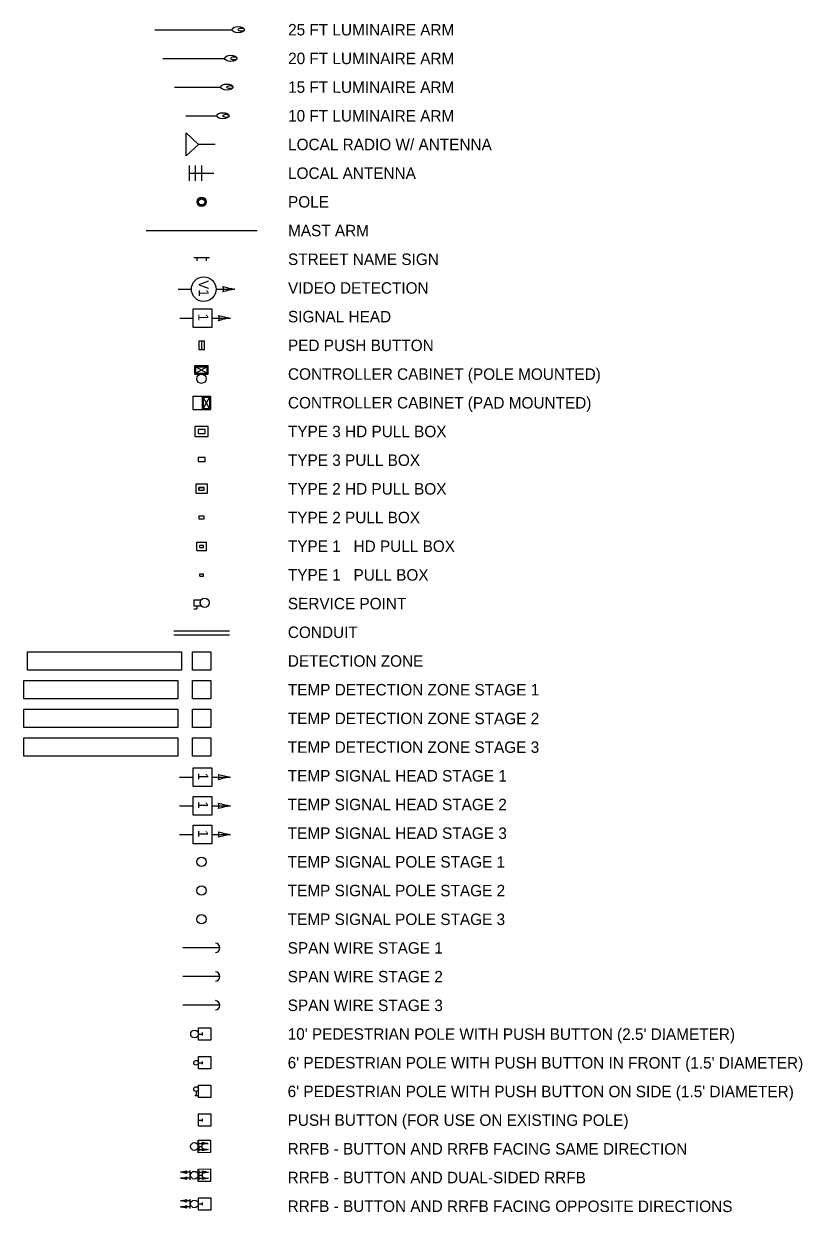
# Model space of a CAD drawing. Extents: x 995815 to 1000702, y 1981720 to 1984760.
# Drawn here: x 997075.9 to 997328.4, y 1983346.4 to 1983731.6 of the extents above; entities that cross this region are included whole.
import ezdxf

# ---------------------------------------------------------------- set-up
doc = ezdxf.new("R2010")
doc.units = 0
for name, color, linetype in [('DSN_Drain_Alignment_ArDOT_BMCD_Rt', 7, 'Continuous'), ('DSN_DRAIN_Analytics', 7, 'Continuous'), ('DSN_DRAIN_Analytics_ArDOT_BMCD_Rt', 7, 'Continuous'), ('DSN_DRAIN_Storm-Sewer_ArDOT_BMCD_Lt', 7, 'Continuous'), ('DSN_DRFT_Common-Annotations', 7, 'Continuous'), ('DSN_DRFT_Const-No-Plot', 7, 'Continuous'), ('DSN_DRFT_Guideline-No-Plot', 7, 'Continuous'), ('DSN_RDWY_Alignment', 7, 'Continuous'), ('DSN_ROW_Point-Name-Annotation', 7, 'Continuous'), ('R_Notes', 7, 'Continuous'), ('TEMP_DETECTION ZONE_STAGE 1', 7, 'Continuous'), ('TEMP_DETECTION ZONE_STAGE 2', 7, 'Continuous'), ('TEMP_DETECTION ZONE_STAGE 3', 7, 'Continuous'), ('TEMP_SIGNAL_HEAD_STAGE 1', 7, 'Continuous'), ('TEMP_SIGNAL_HEAD_STAGE 2', 7, 'Continuous'), ('TEMP_SIGNAL_HEAD_STAGE 3', 7, 'Continuous'), ('TEMP_SIGNAL_POLES_STAGE 1', 7, 'Continuous'), ('TEMP_SIGNAL_POLES_STAGE 2', 7, 'Continuous'), ('TEMP_SIGNAL_POLES_STAGE 3', 7, 'Continuous')]:
    doc.layers.add(name, color=color, linetype=linetype)

msp = doc.modelspace()

# ---------------------------------------------------------------- linework, layer by layer
at = {"layer": 'DSN_Drain_Alignment_ArDOT_BMCD_Rt'}
for p, q in [((997118.45, 1983729.63), (997143.45, 1983729.63)), ((997121.04, 1983720.33), (997141.04, 1983720.33)), ((997124.75, 1983711.03), (997139.75, 1983711.03)), ((997128.47, 1983701.73), (997138.47, 1983701.73)), ((997128.59, 1983688.71), (997128.59, 1983696.21)), ((997128.59, 1983696.21), (997132.59, 1983692.46)), ((997132.59, 1983692.46), (997128.59, 1983688.71)), ((997137.94, 1983692.46), (997132.59, 1983692.46)), ((997129.52, 1983685.62), (997129.52, 1983680.62)), ((997129.52, 1983683.12), (997137.52, 1983683.12)), ((997131.52, 1983685.62), (997131.52, 1983680.62)), ((997133.52, 1983685.62), (997133.52, 1983680.62)), ((997131.35, 1983618.01), (997131.35, 1983620.75)), ((997131.35, 1983620.75), (997135.68, 1983620.75)), ((997135.68, 1983618.01), (997135.68, 1983620.75)), ((997131.35, 1983618.01), (997135.68, 1983618.01)), ((997131.68, 1983620.42), (997135.35, 1983620.42)), ((997131.68, 1983618.34), (997131.68, 1983620.42)), ((997135.35, 1983620.42), (997131.68, 1983618.34)), ((997131.68, 1983618.34), (997135.35, 1983618.34)), ((997131.7, 1983620.42), (997135.35, 1983618.34)), ((997135.35, 1983618.34), (997135.35, 1983620.42)), ((997132, 1983563.59), (997135.18, 1983563.59)), ((997132, 1983560.86), (997132, 1983563.59)), ((997135.18, 1983560.86), (997135.18, 1983563.59)), ((997132, 1983560.86), (997135.18, 1983560.86)), ((997133, 1983561.86), (997133, 1983562.59)), ((997133, 1983562.59), (997134.18, 1983562.59)), ((997133, 1983561.86), (997134.18, 1983561.86)), ((997134.18, 1983561.86), (997134.18, 1983562.59)), ((997133, 1983552.57), (997133, 1983553.3)), ((997133, 1983553.3), (997134.18, 1983553.3)), ((997133, 1983552.57), (997134.18, 1983552.57)), ((997134.18, 1983552.57), (997134.18, 1983553.3))]:
    msp.add_line(p, q, dxfattribs=at)
msp.add_circle((997133.52, 1983616.51), 1.5, dxfattribs=at)
for centre, major_axis in [((997145.45, 1983729.63), (2, 0)), ((997146.45, 1983729.63), (-1, 0)), ((997143.04, 1983720.33), (2, 0)), ((997144.04, 1983720.33), (-1, 0)), ((997141.75, 1983711.03), (2, 0)), ((997142.75, 1983711.03), (-1, 0)), ((997140.47, 1983701.73), (2, 0)), ((997141.47, 1983701.73), (-1, 0))]:
    msp.add_ellipse(centre, major_axis=major_axis, ratio=0.5, dxfattribs=at)
at = {"layer": 'DSN_DRAIN_Analytics'}
for p, q in [((997077.07, 1983528.03), (997127.07, 1983528.03)), ((997077.07, 1983522.03), (997077.07, 1983528.03)), ((997127.07, 1983528.03), (997127.07, 1983522.03)), ((997127.07, 1983522.03), (997077.07, 1983522.03))]:
    msp.add_line(p, q, dxfattribs=at)
msp.add_lwpolyline([(997136.59, 1983522.03), (997130.59, 1983522.03), (997130.59, 1983528.03), (997136.59, 1983528.03)], close=True, dxfattribs=at)
at = {"layer": 'DSN_DRAIN_Analytics_ArDOT_BMCD_Rt'}
for points in [[(997132.54, 1983406.13), (997136.54, 1983406.13), (997136.54, 1983402.13), (997132.54, 1983402.13)], [(997132.53, 1983396.83), (997136.53, 1983396.83), (997136.53, 1983392.83), (997132.53, 1983392.83)], [(997132.53, 1983387.53), (997136.53, 1983387.53), (997136.53, 1983383.53), (997132.53, 1983383.53)], [(997132.52, 1983378.23), (997136.52, 1983378.23), (997136.52, 1983374.23), (997132.52, 1983374.23)], [(997132.48, 1983369.67), (997136.48, 1983369.68), (997136.49, 1983365.68), (997132.49, 1983365.67)], [(997132.5, 1983360.37), (997136.5, 1983360.38), (997136.51, 1983356.38), (997132.51, 1983356.37)], [(997132.52, 1983351.07), (997136.52, 1983351.08), (997136.53, 1983347.08), (997132.53, 1983347.07)]]:
    msp.add_lwpolyline(points, close=True, dxfattribs=at)
at = {"layer": 'DSN_DRAIN_Storm-Sewer_ArDOT_BMCD_Lt'}
for p, q in [((997136.09, 1983655.73), (997131.09, 1983655.73)), ((997132.09, 1983654.73), (997132.09, 1983655.73)), ((997135.09, 1983655.73), (997135.09, 1983654.73)), ((997136.09, 1983655.73), (997135.09, 1983655.73))]:
    msp.add_line(p, q, dxfattribs=at)
at = {"layer": 'DSN_DRFT_Common-Annotations'}
for p, q in [((997135.76, 1983601.06), (997131.43, 1983601.06)), ((997131.43, 1983601.06), (997131.43, 1983597.79)), ((997131.43, 1983597.79), (997135.76, 1983597.79)), ((997132.43, 1983600.06), (997132.43, 1983598.79)), ((997134.76, 1983600.06), (997132.43, 1983600.06)), ((997132.43, 1983598.79), (997134.76, 1983598.79)), ((997134.76, 1983598.79), (997134.76, 1983600.06)), ((997135.76, 1983597.79), (997135.76, 1983601.06)), ((997132.42, 1983590.94), (997132.42, 1983589.67)), ((997134.76, 1983590.94), (997132.42, 1983590.94)), ((997134.76, 1983589.67), (997134.76, 1983590.94)), ((997132.42, 1983589.67), (997134.76, 1983589.67)), ((997135.46, 1983582.29), (997131.71, 1983582.29)), ((997131.71, 1983582.29), (997131.71, 1983579.37)), ((997135.46, 1983579.37), (997135.46, 1983582.29)), ((997131.71, 1983579.37), (997135.46, 1983579.37)), ((997132.71, 1983580.37), (997132.71, 1983581.29)), ((997132.71, 1983581.29), (997134.46, 1983581.29)), ((997132.71, 1983581.29), (997132.71, 1983580.37)), ((997134.46, 1983581.29), (997132.71, 1983581.29)), ((997132.71, 1983580.37), (997134.46, 1983580.37)), ((997132.71, 1983580.37), (997134.46, 1983580.37)), ((997134.46, 1983580.37), (997134.46, 1983581.29)), ((997134.46, 1983580.37), (997134.46, 1983581.29)), ((997132.71, 1983571.99), (997132.71, 1983571.07)), ((997134.46, 1983571.99), (997132.71, 1983571.99)), ((997132.71, 1983571.99), (997132.71, 1983571.07)), ((997134.46, 1983571.99), (997132.71, 1983571.99)), ((997132.71, 1983571.07), (997134.46, 1983571.07)), ((997132.71, 1983571.07), (997134.46, 1983571.07)), ((997134.46, 1983571.07), (997134.46, 1983571.99)), ((997134.46, 1983571.07), (997134.46, 1983571.99)), ((997132.54, 1983404.13), (997133.85, 1983404.13)), ((997133.85, 1983403.7), (997133.85, 1983404.57)), ((997132.53, 1983394.83), (997133.85, 1983394.83)), ((997133.85, 1983394.4), (997133.85, 1983395.27)), ((997131.34, 1983384.21), (997132.21, 1983384.21)), ((997131.78, 1983385.53), (997131.78, 1983384.21)), ((997132.52, 1983376.23), (997133.84, 1983376.23)), ((997133.84, 1983375.8), (997133.84, 1983376.67)), ((997132.49, 1983367.67), (997133.81, 1983367.68)), ((997133.81, 1983367.24), (997133.8, 1983368.11)), ((997133.82, 1983357.94), (997133.82, 1983358.81)), ((997132.5, 1983358.37), (997133.82, 1983358.38)), ((997132.52, 1983349.07), (997133.84, 1983349.08)), ((997133.84, 1983348.64), (997133.84, 1983349.51))]:
    msp.add_line(p, q, dxfattribs=at)
for points in [[(997132.73, 1983628.65), (997132.73, 1983626.02), (997133.6, 1983626.01), (997133.6, 1983628.65)], [(997132.73, 1983626.02), (997134.47, 1983626.01), (997134.48, 1983628.65), (997132.73, 1983628.65)]]:
    msp.add_lwpolyline(points, close=True, dxfattribs=at)
at = {"layer": 'DSN_DRFT_Const-No-Plot'}
for p, q in [((997130.73, 1983610.9), (997136.47, 1983610.9)), ((997130.73, 1983610.9), (997130.73, 1983606.57)), ((997133.73, 1983610.9), (997133.73, 1983606.57)), ((997134.06, 1983610.57), (997134.06, 1983606.9)), ((997136.14, 1983606.9), (997134.06, 1983610.57)), ((997134.06, 1983610.57), (997136.14, 1983610.57)), ((997136.14, 1983610.55), (997134.06, 1983606.9)), ((997136.14, 1983610.57), (997136.14, 1983606.9)), ((997136.47, 1983610.9), (997136.47, 1983606.57)), ((997130.73, 1983606.57), (997136.47, 1983606.57)), ((997134.06, 1983606.9), (997136.14, 1983606.9))]:
    msp.add_line(p, q, dxfattribs=at)
at = {"layer": 'DSN_DRFT_Guideline-No-Plot'}
for p, q in [((997125.94, 1983645.54), (997130.27, 1983645.54)), ((997138.27, 1983645.54), (997144.33, 1983645.54)), ((997126.53, 1983636.16), (997130.87, 1983636.16)), ((997136.94, 1983636.19), (997142.98, 1983636.19))]:
    msp.add_line(p, q, dxfattribs=at)
msp.add_lwpolyline([(997130.87, 1983633.15), (997130.87, 1983639.21), (997136.94, 1983639.21), (997136.94, 1983633.15)], close=True, dxfattribs=at)
msp.add_circle((997134.27, 1983645.54), 4, dxfattribs=at)
for centre, radius, start, end in [((997139.06, 1983645.54), 1.63, 328.1527, 31.8473), ((997148.74, 1983674.68), 29.47, 253.6536, 261.3917), ((997148.74, 1983616.4), 29.47, 98.6083, 106.3464), ((997137.71, 1983636.19), 1.63, 328.1527, 31.8473), ((997147.39, 1983665.33), 29.47, 253.6536, 261.3917), ((997147.39, 1983607.04), 29.47, 98.6083, 106.3464)]:
    msp.add_arc(centre, radius, start, end, dxfattribs=at)
at = {"layer": 'DSN_RDWY_Alignment'}
for p, q in [((997131.08, 1983544.89), (997131.08, 1983542.89)), ((997131.08, 1983544.89), (997133.08, 1983544.89)), ((997133.08, 1983544.89), (997133.08, 1983542.89)), ((997131.08, 1983542.89), (997133.08, 1983542.89)), ((997131.08, 1983541.89), (997132.08, 1983541.89)), ((997132.08, 1983542.89), (997132.08, 1983541.89)), ((997124.52, 1983534.83), (997142.65, 1983534.83)), ((997124.52, 1983533.5), (997142.65, 1983533.5))]:
    msp.add_line(p, q, dxfattribs=at)
msp.add_circle((997134.58, 1983543.89), 1.5, dxfattribs=at)
at = {"layer": 'DSN_ROW_Point-Name-Annotation'}
for p, q in [((997115.59, 1983664.54), (997151.59, 1983664.54)), ((997132.49, 1983367.67), (997132.74, 1983367.67)), ((997132.74, 1983366.17), (997132.73, 1983369.17)), ((997132.74, 1983368.67), (997135.76, 1983368.68)), ((997132.74, 1983366.67), (997135.76, 1983366.68)), ((997129.75, 1983359.37), (997126.73, 1983359.36)), ((997129.75, 1983359.87), (997129.76, 1983356.87)), ((997132.76, 1983356.87), (997132.75, 1983359.87)), ((997132.75, 1983359.37), (997135.77, 1983359.38)), ((997129.76, 1983357.37), (997126.74, 1983357.36)), ((997130, 1983358.37), (997129.75, 1983358.37)), ((997132.5, 1983358.37), (997132.75, 1983358.37)), ((997132.76, 1983357.37), (997135.78, 1983357.38)), ((997129.77, 1983350.08), (997126.75, 1983350.07)), ((997129.77, 1983348.08), (997126.75, 1983348.07)), ((997129.77, 1983350.58), (997129.77, 1983347.58)), ((997130.02, 1983349.08), (997129.77, 1983349.08))]:
    msp.add_line(p, q, dxfattribs=at)
for centre, radius in [((997133.59, 1983673.84), 1.5), ((997133.59, 1983673.84), 1.25), ((997133.59, 1983673.84), 1), ((997133.55, 1983459.93), 1.5), ((997131.29, 1983404.14), 1.25), ((997131.78, 1983394.83), 0.75), ((997131.78, 1983386.28), 0.75), ((997131.24, 1983367.67), 1.25), ((997131.25, 1983358.37), 1.25), ((997131.27, 1983349.07), 1.25)]:
    msp.add_circle(centre, radius, dxfattribs=at)
for centre, radius, start, end in [((997133.12, 1983368.67), 0.814, 328.2824, 31.977), ((997137.93, 1983383.25), 14.74, 253.7833, 261.5214), ((997137.99, 1983354.11), 14.74, 98.738, 106.4762), ((997133.13, 1983366.67), 0.814, 328.2824, 31.977), ((997137.93, 1983381.25), 14.74, 253.7833, 261.5214), ((997138, 1983352.11), 14.74, 98.738, 106.4762), ((997124.49, 1983373.93), 14.74, 278.738, 286.4762), ((997124.56, 1983344.79), 14.74, 73.7833, 81.5214), ((997129.37, 1983359.37), 0.814, 148.2824, 211.977), ((997133.14, 1983359.37), 0.814, 328.2824, 31.977), ((997137.95, 1983373.95), 14.74, 253.7833, 261.5214), ((997138.01, 1983344.81), 14.74, 98.738, 106.4762), ((997124.5, 1983371.93), 14.74, 278.738, 286.4762), ((997124.56, 1983342.79), 14.74, 73.7833, 81.5214), ((997129.37, 1983357.37), 0.814, 148.2824, 211.977), ((997133.14, 1983357.37), 0.814, 328.2824, 31.977), ((997137.95, 1983371.95), 14.74, 253.7833, 261.5214), ((997138.02, 1983342.81), 14.74, 98.738, 106.4762), ((997124.51, 1983364.64), 14.74, 278.738, 286.4762), ((997124.58, 1983335.5), 14.74, 73.7833, 81.5214), ((997124.51, 1983362.64), 14.74, 278.738, 286.4762), ((997124.58, 1983333.5), 14.74, 73.7833, 81.5214), ((997129.38, 1983350.08), 0.814, 148.2824, 211.977), ((997129.39, 1983348.08), 0.814, 148.2824, 211.977)]:
    msp.add_arc(centre, radius, start, end, dxfattribs=at)
at = {"layer": 'TEMP_DETECTION ZONE_STAGE 1'}
for p, q in [((997075.91, 1983518.73), (997125.91, 1983518.73)), ((997075.91, 1983512.73), (997075.91, 1983518.73)), ((997125.91, 1983518.73), (997125.91, 1983512.73)), ((997125.91, 1983512.73), (997075.91, 1983512.73))]:
    msp.add_line(p, q, dxfattribs=at)
msp.add_lwpolyline([(997136.59, 1983512.73), (997130.59, 1983512.73), (997130.59, 1983518.73), (997136.59, 1983518.73)], close=True, dxfattribs=at)
at = {"layer": 'TEMP_DETECTION ZONE_STAGE 2'}
for p, q in [((997075.91, 1983509.43), (997125.91, 1983509.43)), ((997075.91, 1983503.43), (997075.91, 1983509.43)), ((997125.91, 1983509.43), (997125.91, 1983503.43)), ((997125.91, 1983503.43), (997075.91, 1983503.43))]:
    msp.add_line(p, q, dxfattribs=at)
msp.add_lwpolyline([(997136.58, 1983503.43), (997130.58, 1983503.43), (997130.58, 1983509.43), (997136.58, 1983509.43)], close=True, dxfattribs=at)
at = {"layer": 'TEMP_DETECTION ZONE_STAGE 3'}
for p, q in [((997075.9, 1983500.13), (997125.9, 1983500.13)), ((997075.9, 1983494.13), (997075.9, 1983500.13)), ((997125.9, 1983500.13), (997125.9, 1983494.13)), ((997125.9, 1983494.13), (997075.9, 1983494.13))]:
    msp.add_line(p, q, dxfattribs=at)
msp.add_lwpolyline([(997136.58, 1983494.13), (997130.58, 1983494.13), (997130.58, 1983500.13), (997136.58, 1983500.13)], close=True, dxfattribs=at)
at = {"layer": 'TEMP_SIGNAL_HEAD_STAGE 1'}
for p, q in [((997126.46, 1983487.36), (997130.81, 1983487.36)), ((997136.87, 1983487.39), (997142.91, 1983487.39))]:
    msp.add_line(p, q, dxfattribs=at)
msp.add_lwpolyline([(997130.81, 1983484.35), (997130.81, 1983490.41), (997136.87, 1983490.41), (997136.87, 1983484.35)], close=True, dxfattribs=at)
for centre, radius, start, end in [((997137.64, 1983487.39), 1.63, 328.1527, 31.8473), ((997147.32, 1983516.53), 29.47, 253.6536, 261.3917), ((997147.32, 1983458.24), 29.47, 98.6083, 106.3464)]:
    msp.add_arc(centre, radius, start, end, dxfattribs=at)
at = {"layer": 'TEMP_SIGNAL_HEAD_STAGE 2'}
for p, q in [((997126.46, 1983478.06), (997130.8, 1983478.06)), ((997136.87, 1983478.09), (997142.91, 1983478.09))]:
    msp.add_line(p, q, dxfattribs=at)
msp.add_lwpolyline([(997130.8, 1983475.05), (997130.8, 1983481.11), (997136.87, 1983481.11), (997136.87, 1983475.05)], close=True, dxfattribs=at)
for centre, radius, start, end in [((997137.64, 1983478.09), 1.63, 328.1527, 31.8473), ((997147.32, 1983507.23), 29.47, 253.6536, 261.3917), ((997147.32, 1983448.94), 29.47, 98.6083, 106.3464)]:
    msp.add_arc(centre, radius, start, end, dxfattribs=at)
at = {"layer": 'TEMP_SIGNAL_HEAD_STAGE 3'}
for p, q in [((997126.45, 1983468.76), (997130.8, 1983468.76)), ((997136.86, 1983468.79), (997142.9, 1983468.79))]:
    msp.add_line(p, q, dxfattribs=at)
msp.add_lwpolyline([(997130.8, 1983465.75), (997130.8, 1983471.81), (997136.86, 1983471.81), (997136.86, 1983465.75)], close=True, dxfattribs=at)
for centre, radius, start, end in [((997137.64, 1983468.79), 1.63, 328.1527, 31.8473), ((997147.31, 1983497.93), 29.47, 253.6536, 261.3917), ((997147.31, 1983439.64), 29.47, 98.6083, 106.3464)]:
    msp.add_arc(centre, radius, start, end, dxfattribs=at)
at = {"layer": 'TEMP_SIGNAL_POLES_STAGE 1'}
msp.add_line((997139.54, 1983432.04), (997127.54, 1983432.04), dxfattribs=at)
msp.add_arc((997138.04, 1983432.04), 1.5, 270, 90, dxfattribs=at)
at = {"layer": 'TEMP_SIGNAL_POLES_STAGE 2'}
msp.add_line((997139.54, 1983422.74), (997127.54, 1983422.74), dxfattribs=at)
msp.add_circle((997133.55, 1983450.63), 1.5, dxfattribs=at)
msp.add_arc((997138.04, 1983422.74), 1.5, 270, 90, dxfattribs=at)
at = {"layer": 'TEMP_SIGNAL_POLES_STAGE 3'}
msp.add_line((997139.54, 1983413.44), (997127.54, 1983413.44), dxfattribs=at)
msp.add_circle((997133.54, 1983441.33), 1.5, dxfattribs=at)
msp.add_arc((997138.04, 1983413.44), 1.5, 270, 90, dxfattribs=at)

# ---------------------------------------------------------------- texts
at = {"layer": 'DSN_DRFT_Guideline-No-Plot'}
for s, p in [('V1', (997132.67, 1983648.43)), ('1', (997132.52, 1983637.65))]:
    msp.add_text(s, height=3.25, rotation=270, dxfattribs=at).set_placement(p)
at = {"layer": 'R_Notes'}
for s, p in [('25 FT LUMINAIRE ARM', (997161.63, 1983727.78)), ('20 FT LUMINAIRE ARM', (997161.63, 1983718.48)), ('15 FT LUMINAIRE ARM', (997161.63, 1983709.18)), ('10 FT LUMINAIRE ARM', (997161.62, 1983699.88)), ('LOCAL RADIO W/ ANTENNA', (997161.62, 1983690.58)), ('LOCAL ANTENNA', (997161.61, 1983681.28)), ('POLE', (997161.61, 1983671.98)), ('MAST ARM', (997161.61, 1983662.68)), ('STREET NAME SIGN', (997161.6, 1983653.38)), ('VIDEO DETECTION', (997161.6, 1983644.08)), ('SIGNAL HEAD', (997161.59, 1983634.78)), ('PED PUSH BUTTON', (997161.59, 1983625.48)), ('CONTROLLER CABINET (POLE MOUNTED)', (997161.59, 1983616.18)), ('CONTROLLER CABINET (PAD MOUNTED)', (997161.58, 1983606.88)), ('TYPE 3 HD PULL BOX', (997161.58, 1983597.58)), ('TYPE 3 PULL BOX', (997161.57, 1983588.28)), ('TYPE 2 HD PULL BOX', (997161.57, 1983578.98)), ('TYPE 2 PULL BOX', (997161.57, 1983569.68)), ('TYPE 1   HD PULL BOX', (997161.56, 1983560.38)), ('TYPE 1   PULL BOX', (997161.56, 1983551.08)), ('SERVICE POINT', (997161.55, 1983541.78)), ('CONDUIT', (997161.55, 1983532.48)), ('DETECTION ZONE', (997161.54, 1983523.18)), ('TEMP DETECTION ZONE STAGE 1', (997161.54, 1983513.88)), ('TEMP DETECTION ZONE STAGE 2', (997161.54, 1983504.58)), ('TEMP DETECTION ZONE STAGE 3', (997161.53, 1983495.28)), ('TEMP SIGNAL HEAD STAGE 1', (997161.53, 1983485.98)), ('TEMP SIGNAL HEAD STAGE 2', (997161.52, 1983476.68)), ('TEMP SIGNAL HEAD STAGE 3', (997161.52, 1983467.38)), ('TEMP SIGNAL POLE STAGE 1', (997161.52, 1983458.08)), ('TEMP SIGNAL POLE STAGE 2', (997161.51, 1983448.78)), ('TEMP SIGNAL POLE STAGE 3', (997161.51, 1983439.48)), ('SPAN WIRE STAGE 1', (997161.5, 1983430.18)), ('SPAN WIRE STAGE 2', (997161.5, 1983420.88)), ('SPAN WIRE STAGE 3', (997161.5, 1983411.58)), ("10' PEDESTRIAN POLE WITH PUSH BUTTON (2.5' DIAMETER)", (997161.49, 1983402.28)), ("6' PEDESTRIAN POLE WITH PUSH BUTTON IN FRONT (1.5' DIAMETER)", (997161.49, 1983392.98)), ("6' PEDESTRIAN POLE WITH PUSH BUTTON ON SIDE (1.5' DIAMETER)", (997161.48, 1983383.68)), ('PUSH BUTTON (FOR USE ON EXISTING POLE)', (997161.48, 1983374.38)), ('RRFB - BUTTON AND RRFB FACING SAME DIRECTION', (997161.48, 1983365.08)), ('RRFB - BUTTON AND DUAL-SIDED RRFB', (997161.47, 1983355.78)), ('RRFB - BUTTON AND RRFB FACING OPPOSITE DIRECTIONS', (997161.47, 1983346.48))]:
    msp.add_text(s, height=3.72, rotation=359.9748, dxfattribs=at).set_placement(p)
at = {"layer": 'TEMP_SIGNAL_HEAD_STAGE 1'}
msp.add_text('1', height=3.25, rotation=270, dxfattribs=at).set_placement((997132.46, 1983488.85))
at = {"layer": 'TEMP_SIGNAL_HEAD_STAGE 2'}
msp.add_text('1', height=3.25, rotation=270, dxfattribs=at).set_placement((997132.45, 1983479.55))
at = {"layer": 'TEMP_SIGNAL_HEAD_STAGE 3'}
msp.add_text('1', height=3.25, rotation=270, dxfattribs=at).set_placement((997132.45, 1983470.25))

doc.saveas('drawing.dxf')
